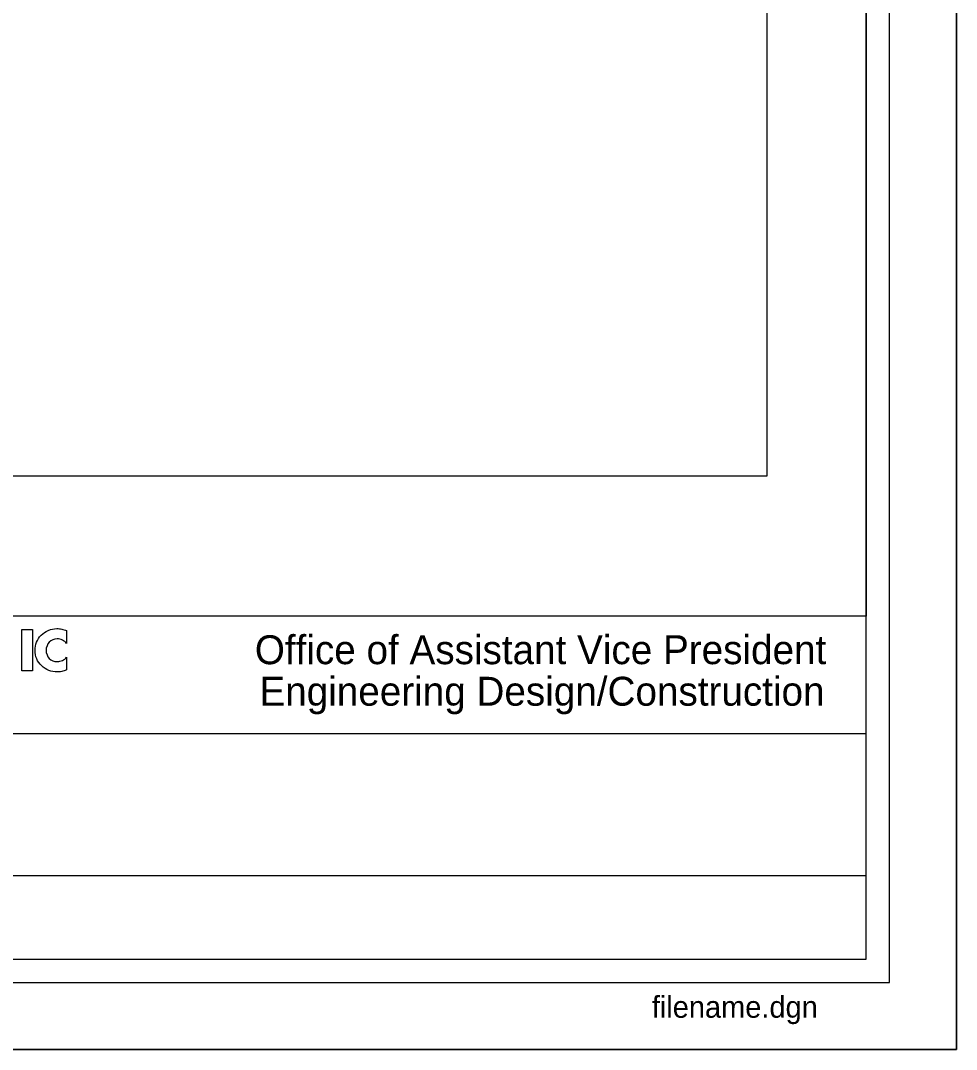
# Model space of a CAD drawing. Extents: x 0 to 1.42, y 0 to 0.92.
# Drawn here: x 1.2008 to 1.4167, y 0 to 0.2374 of the extents above; entities that cross this region are included whole.
import ezdxf

# ---------------------------------------------------------------- set-up
doc = ezdxf.new("R2010")
doc.units = 0
for name, color, linetype in [('C-ANNO-NPLT', 7, 'Continuous'), ('Default', 7, 'Continuous'), ('G-ANNO-TTLB-TRIM', 7, 'Continuous'), ('G-BORDER', 7, 'Continuous')]:
    doc.layers.add(name, color=color, linetype=linetype)

msp = doc.modelspace()

# ---------------------------------------------------------------- linework, layer by layer
at = {"layer": 'C-ANNO-NPLT'}
msp.add_lwpolyline([(0.08124, 0.46563), (1.37291, 0.46563), (1.37291, 0.13229), (0.08124, 0.13229)], close=True, dxfattribs=at)
at = {"layer": 'Default'}
msp.add_line((1.39583, 0.49792), (1.39583, 0.1), dxfattribs=at)
at = {"layer": 'G-ANNO-TTLB-TRIM'}
msp.add_lwpolyline([(0, 0), (1.41666, 0), (1.41666, 0.91666), (0, 0.91666)], close=True, dxfattribs=at)
at = {"layer": 'G-BORDER'}
for p, q in [((1.39583, 0.1), (0.98967, 0.1)), ((1.2011, 0.08736), (1.2011, 0.09688)), ((1.2011, 0.09688), (1.20358, 0.09688)), ((1.20358, 0.09688), (1.20358, 0.08736)), ((1.21145, 0.09664), (1.21145, 0.09366)), ((1.21145, 0.0905), (1.21145, 0.08755)), ((1.20358, 0.08736), (1.2011, 0.08736)), ((1.11993, 0.07292), (1.39583, 0.07292)), ((1.11993, 0.04013), (1.39583, 0.04013))]:
    msp.add_line(p, q, dxfattribs=at)
for points in [[(0, 0.91666), (1.41666, 0.91666), (1.41666, 0), (0, 0)], [(0.01375, 0.01542), (1.40124, 0.01542), (1.40124, 0.90125), (0.01375, 0.90125)], [(0.05833, 0.02084), (1.39583, 0.02084), (1.39583, 0.89583), (0.05833, 0.89583)]]:
    msp.add_lwpolyline(points, close=True, dxfattribs=at)
for points in [[(1.20418, 0.09209), (1.20418, 0.09256), (1.20426, 0.09304), (1.20437, 0.09351), (1.20452, 0.09398), (1.20471, 0.09439), (1.20494, 0.09481), (1.20523, 0.0952), (1.20557, 0.09557)], [(1.20557, 0.09557), (1.20594, 0.09591), (1.20633, 0.0962), (1.20677, 0.09646), (1.20722, 0.09669), (1.20771, 0.09688), (1.20818, 0.09698), (1.20868, 0.09706), (1.2092, 0.09711)], [(1.2092, 0.09711), (1.20949, 0.09709), (1.20978, 0.09706), (1.21007, 0.09703), (1.21033, 0.09698), (1.21061, 0.0969), (1.21088, 0.09683), (1.21116, 0.09672), (1.21145, 0.09664)], [(1.20928, 0.09473), (1.20873, 0.09466), (1.20824, 0.09453), (1.20779, 0.09426), (1.20742, 0.09395), (1.20714, 0.09356), (1.20693, 0.09311), (1.20677, 0.09262), (1.20675, 0.09209)], [(1.21145, 0.09366), (1.21124, 0.0939), (1.21101, 0.09411), (1.21077, 0.09429), (1.21048, 0.09445), (1.2102, 0.09458), (1.20991, 0.09466), (1.20959, 0.09471), (1.20928, 0.09473)], [(1.2057, 0.08851), (1.20533, 0.08888), (1.20502, 0.08927), (1.20476, 0.08966), (1.20455, 0.09011), (1.20437, 0.09058), (1.20426, 0.09105), (1.20418, 0.09157), (1.20418, 0.09209)], [(1.20675, 0.09209), (1.20677, 0.09155), (1.20693, 0.09105), (1.20714, 0.0906), (1.20745, 0.09021), (1.20782, 0.08992), (1.20826, 0.08969), (1.20876, 0.08953), (1.20933, 0.08951)], [(1.20933, 0.08951), (1.20962, 0.08951), (1.20991, 0.08956), (1.2102, 0.08964), (1.21048, 0.08977), (1.21074, 0.0899), (1.21101, 0.09008), (1.21124, 0.09026), (1.21145, 0.0905)], [(1.20928, 0.0871), (1.20878, 0.0871), (1.20829, 0.08718), (1.20782, 0.08728), (1.20735, 0.08744), (1.2069, 0.08765), (1.20648, 0.08789), (1.20607, 0.08817), (1.2057, 0.08851)], [(1.21145, 0.08755), (1.21114, 0.08744), (1.21088, 0.08736), (1.21059, 0.08728), (1.21033, 0.08721), (1.21007, 0.08715), (1.2098, 0.08713), (1.20954, 0.0871), (1.20928, 0.0871)]]:
    msp.add_lwpolyline(points, dxfattribs=at)

# ---------------------------------------------------------------- texts
for s, p in [('Office of Assistant Vice President', (1.25486, 0.08889)), ('Engineering Design/Construction', (1.25592, 0.07931))]:
    msp.add_text(s, height=0.0066667, rotation=0.004, dxfattribs=at).set_placement(p)
msp.add_text('filename.dgn', height=0.005, dxfattribs=at).set_placement((1.34641, 0.00731))

doc.saveas('drawing.dxf')
